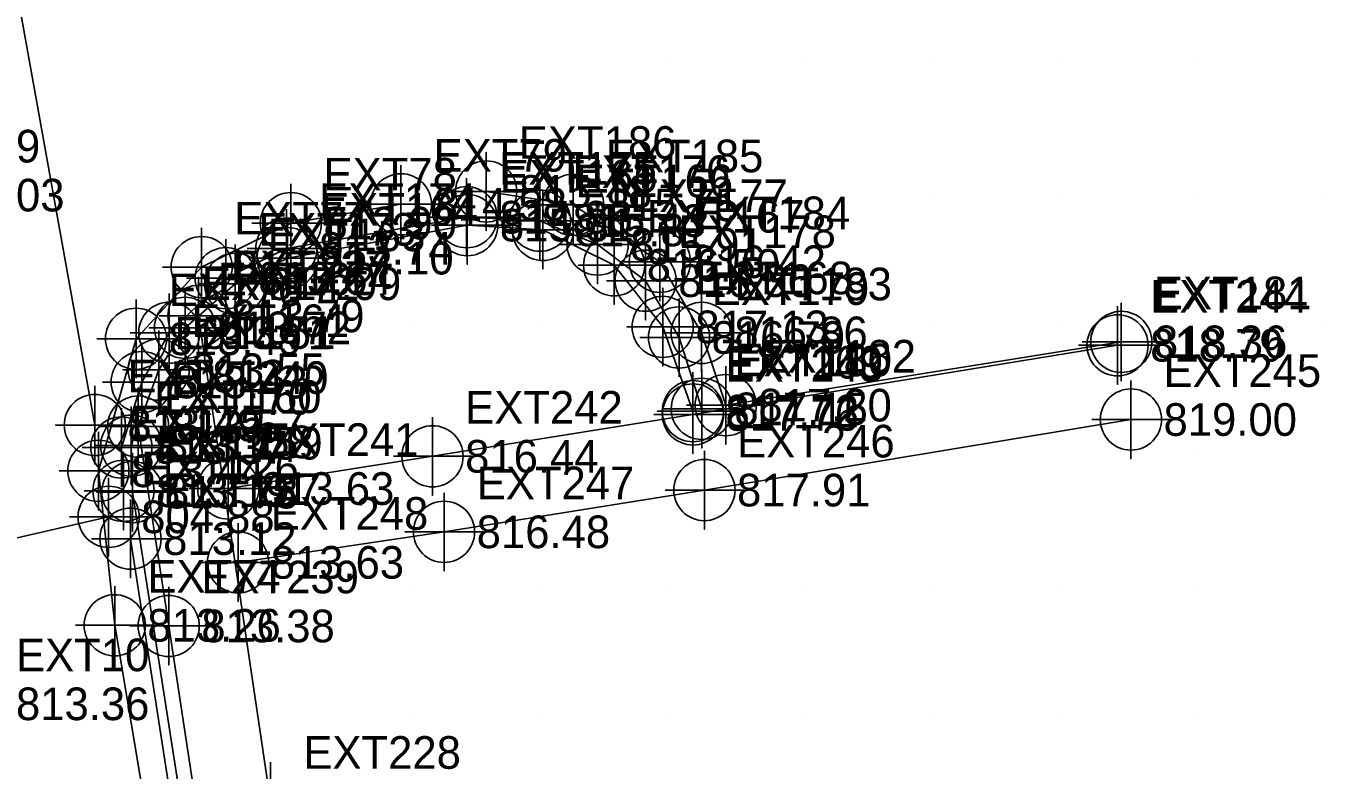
# Model space of a CAD drawing. Extents: x 1762120 to 1766775, y 709485 to 712965.
# Drawn here: x 1763810.5 to 1763910, y 712815.9 to 712872.9 of the extents above; entities that cross this region are included whole.
import ezdxf

# ---------------------------------------------------------------- set-up
doc = ezdxf.new("R2010")
doc.units = 0
for name, color, linetype in [('Exist DTM Drainline', 7, 'Continuous'), ('Exist DTM Drainline Cogo Elevation', 7, 'Continuous'), ('Exist DTM Drainline Cogo Number', 7, 'Continuous'), ('Exist DTM Drainline Cogo Point CELL', 7, 'Continuous'), ('Exist DTM QL2 LIDAR Elevation Point', 7, 'Continuous'), ('Exist Roads Curbs', 7, 'Continuous'), ('Exist Roads Curbs Cogo Elevation', 7, 'Continuous'), ('Exist Roads Curbs Cogo Number', 7, 'Continuous'), ('Exist Roads Curbs Cogo Point CELL', 7, 'Continuous'), ('Exist Roads EOP', 7, 'Continuous'), ('Exist Roads EOP Cogo Elevation', 7, 'Continuous'), ('Exist Roads EOP Cogo Number', 7, 'Continuous'), ('Exist Roads EOP Cogo Point CELL', 7, 'Continuous'), ('Exist Roads EOP Other', 7, 'Continuous'), ('Exist Roads EOP Other Cogo Elevation', 7, 'Continuous'), ('Exist Roads EOP Other Cogo Number', 7, 'Continuous'), ('Exist Roads EOP Other Cogo Point CELL', 7, 'Continuous'), ('Exist Roads EOT', 7, 'Continuous'), ('Exist Roads EOT Cogo Elevation', 7, 'Continuous'), ('Exist Roads EOT Cogo Number', 7, 'Continuous'), ('Exist Roads EOT Cogo Point CELL', 7, 'Continuous'), ('Exist Structure Minor Pipes RCP 15 Inch', 7, 'Continuous'), ('Exist Structure Minor Pipes RCP 15 Inch Cogo Elevation', 7, 'Continuous'), ('Exist Structure Minor Pipes RCP 15 Inch Cogo Number', 7, 'Continuous'), ('Exist Structure Minor Pipes RCP 15 Inch Cogo Point CELL', 7, 'Continuous')]:
    doc.layers.add(name, color=color, linetype=linetype)

msp = doc.modelspace()

# ---------------------------------------------------------------- linework, layer by layer
at = {"layer": 'Exist DTM Drainline'}
for points in [[(1763817.989, 712837.279), (1763817.834, 712840.601), (1763819.388, 712845.611), (1763821.503, 712849.398), (1763825.83, 712853.572), (1763830.477, 712855.852), (1763844.289, 712858.245), (1763849.91, 712857.978), (1763854.328, 712856.151), (1763858.009, 712853.381), (1763860.57, 712849.03), (1763862.311, 712843.559)], [(1763888.176, 712675.965), (1763883.465, 712673.426), (1763879.421, 712672.239), (1763861.295, 712669.219), (1763855.834, 712669.139), (1763849.992, 712671.404), (1763845.815, 712675.27), (1763843.641, 712680.197), (1763837.254, 712719.085), (1763830.877, 712756.626), (1763824.422, 712795.511), (1763818.53, 712833.611)]]:
    msp.add_lwpolyline(points, dxfattribs=at)
at = {"layer": 'Exist DTM Drainline Cogo Point CELL'}
for points in [[(1763844.289, 712861.245), (1763844.289, 712855.245), (1763844.289, 712858.245), (1763847.289, 712858.245), (1763841.289, 712858.245)], [(1763849.91, 712860.978), (1763849.91, 712854.978), (1763849.91, 712857.978), (1763852.91, 712857.978), (1763846.91, 712857.978)], [(1763830.477, 712858.852), (1763830.477, 712852.852), (1763830.477, 712855.852), (1763833.477, 712855.852), (1763827.477, 712855.852)], [(1763854.328, 712859.151), (1763854.328, 712853.151), (1763854.328, 712856.151), (1763857.328, 712856.151), (1763851.328, 712856.151)], [(1763825.83, 712856.572), (1763825.83, 712850.572), (1763825.83, 712853.572), (1763828.83, 712853.572), (1763822.83, 712853.572)], [(1763858.009, 712856.381), (1763858.009, 712850.381), (1763858.009, 712853.381), (1763861.009, 712853.381), (1763855.009, 712853.381)], [(1763821.503, 712852.398), (1763821.503, 712846.398), (1763821.503, 712849.398), (1763824.503, 712849.398), (1763818.503, 712849.398)], [(1763860.57, 712852.03), (1763860.57, 712846.03), (1763860.57, 712849.03), (1763863.57, 712849.03), (1763857.57, 712849.03)], [(1763819.388, 712848.611), (1763819.388, 712842.611), (1763819.388, 712845.611), (1763822.388, 712845.611), (1763816.388, 712845.611)], [(1763862.311, 712846.559), (1763862.311, 712840.559), (1763862.311, 712843.559), (1763865.311, 712843.559), (1763859.311, 712843.559)], [(1763817.834, 712843.601), (1763817.834, 712837.601), (1763817.834, 712840.601), (1763820.834, 712840.601), (1763814.834, 712840.601)], [(1763817.989, 712840.279), (1763817.989, 712834.279), (1763817.989, 712837.279), (1763820.989, 712837.279), (1763814.989, 712837.279)], [(1763818.53, 712836.611), (1763818.53, 712830.611), (1763818.53, 712833.611), (1763821.53, 712833.611), (1763815.53, 712833.611)]]:
    msp.add_lwpolyline(points, dxfattribs=at)
for centre in [(1763844.289, 712858.245), (1763849.91, 712857.978), (1763830.477, 712855.852), (1763854.328, 712856.151), (1763825.83, 712853.572), (1763858.009, 712853.381), (1763821.503, 712849.398), (1763860.57, 712849.03), (1763819.388, 712845.611), (1763862.311, 712843.559), (1763817.834, 712840.601), (1763817.989, 712837.279), (1763818.53, 712833.611)]:
    msp.add_circle(centre, 2.344, dxfattribs=at)
at = {"layer": 'Exist DTM QL2 LIDAR Elevation Point'}
for p, q in [((1763860, 712870), (1763860, 712870)), ((1763870, 712870), (1763870, 712870)), ((1763880, 712870), (1763880, 712870)), ((1763890, 712870), (1763890, 712870)), ((1763900, 712870), (1763900, 712870)), ((1763860, 712860), (1763860, 712860)), ((1763870, 712860), (1763870, 712860)), ((1763880, 712860), (1763880, 712860)), ((1763890, 712860), (1763890, 712860)), ((1763900, 712860), (1763900, 712860)), ((1763910, 712860), (1763910, 712860)), ((1763840, 712850), (1763840, 712850)), ((1763850, 712850), (1763850, 712850)), ((1763880, 712850), (1763880, 712850)), ((1763890, 712850), (1763890, 712850)), ((1763900, 712850), (1763900, 712850)), ((1763910, 712850), (1763910, 712850)), ((1763840, 712840), (1763840, 712840)), ((1763900, 712840), (1763900, 712840)), ((1763840, 712830), (1763840, 712830)), ((1763850, 712830), (1763850, 712830)), ((1763860, 712830), (1763860, 712830)), ((1763870, 712830), (1763870, 712830)), ((1763880, 712830), (1763880, 712830)), ((1763890, 712830), (1763890, 712830)), ((1763900, 712830), (1763900, 712830)), ((1763840, 712820), (1763840, 712820)), ((1763850, 712820), (1763850, 712820)), ((1763860, 712820), (1763860, 712820)), ((1763870, 712820), (1763870, 712820)), ((1763880, 712820), (1763880, 712820)), ((1763890, 712820), (1763890, 712820)), ((1763900, 712820), (1763900, 712820))]:
    msp.add_line(p, q, dxfattribs=at)
at = {"layer": 'Exist Roads Curbs'}
msp.add_lwpolyline([(1763887.913, 712676.609), (1763883.105, 712673.993), (1763879.529, 712672.953), (1763861.13, 712669.797), (1763855.716, 712669.958), (1763851.546, 712671.351), (1763848.135, 712673.751), (1763845.524, 712677.19), (1763844.339, 712680.601), (1763837.881, 712719.135), (1763831.693, 712756.599), (1763825.169, 712795.603), (1763818.676, 712837.176), (1763818.589, 712840.745), (1763820.694, 712846.562), (1763822.71, 712849.767), (1763826.551, 712853.145), (1763830.571, 712855.107), (1763844.339, 712857.64), (1763850.134, 712857.271), (1763855.594, 712854.564), (1763859.316, 712849.842), (1763861.632, 712843.383)], dxfattribs=at)
at = {"layer": 'Exist Roads Curbs Cogo Point CELL'}
for points in [[(1763844.339, 712860.64), (1763844.339, 712854.64), (1763844.339, 712857.64), (1763841.609, 712857.64), (1763847.339, 712857.64)], [(1763850.134, 712860.271), (1763850.134, 712854.271), (1763850.134, 712857.271), (1763847.404, 712857.271), (1763853.134, 712857.271)], [(1763830.571, 712858.107), (1763830.571, 712852.107), (1763830.571, 712855.107), (1763827.841, 712855.107), (1763833.571, 712855.107)], [(1763855.594, 712857.564), (1763855.594, 712851.564), (1763855.594, 712854.564), (1763852.864, 712854.564), (1763858.594, 712854.564)], [(1763826.551, 712856.145), (1763826.551, 712850.145), (1763826.551, 712853.145), (1763823.821, 712853.145), (1763829.551, 712853.145)], [(1763822.71, 712852.767), (1763822.71, 712846.767), (1763822.71, 712849.767), (1763819.98, 712849.767), (1763825.71, 712849.767)], [(1763859.316, 712852.842), (1763859.316, 712846.842), (1763859.316, 712849.842), (1763856.586, 712849.842), (1763862.316, 712849.842)], [(1763820.694, 712849.562), (1763820.694, 712843.562), (1763820.694, 712846.562), (1763817.964, 712846.562), (1763823.694, 712846.562)], [(1763861.632, 712846.383), (1763861.632, 712840.383), (1763861.632, 712843.383), (1763858.902, 712843.383), (1763864.632, 712843.383)], [(1763818.589, 712843.745), (1763818.589, 712837.745), (1763818.589, 712840.745), (1763815.859, 712840.745), (1763821.589, 712840.745)], [(1763818.676, 712840.176), (1763818.676, 712834.176), (1763818.676, 712837.176), (1763815.946, 712837.176), (1763821.676, 712837.176)]]:
    msp.add_lwpolyline(points, dxfattribs=at)
for centre in [(1763844.339, 712857.64), (1763850.134, 712857.271), (1763830.571, 712855.107), (1763855.594, 712854.564), (1763826.551, 712853.145), (1763822.71, 712849.767), (1763859.316, 712849.842), (1763820.694, 712846.562), (1763861.632, 712843.383), (1763818.589, 712840.745), (1763818.676, 712837.176)]:
    msp.add_circle(centre, 2.344, dxfattribs=at)
at = {"layer": 'Exist Roads EOP'}
for points in [[(1763894.461, 712848.693), (1763864.149, 712843.843), (1763862.303, 712849.38), (1763859.101, 712854.83), (1763852.452, 712859.194), (1763845.79, 712860.221)], [(1763872.939, 712669.264), (1763861.771, 712667.397), (1763856.129, 712667.205), (1763850.394, 712669.068), (1763848.283, 712670.385), (1763843.436, 712675.406), (1763841.767, 712679.86), (1763835.931, 712715.544), (1763829.184, 712756.072), (1763822.427, 712796.443), (1763817.324, 712826.974), (1763816.07, 712838.811), (1763818.954, 712848.93), (1763823.982, 712854.424), (1763830.822, 712857.794), (1763839.256, 712859.239)]]:
    msp.add_lwpolyline(points, dxfattribs=at)
at = {"layer": 'Exist Roads EOP Cogo Point CELL'}
for points in [[(1763845.79, 712863.221), (1763845.79, 712857.221), (1763845.79, 712860.221), (1763848.79, 712860.221), (1763842.79, 712860.221)], [(1763839.256, 712862.239), (1763839.256, 712856.239), (1763839.256, 712859.239), (1763842.256, 712859.239), (1763836.256, 712859.239)], [(1763852.452, 712862.194), (1763852.452, 712856.194), (1763852.452, 712859.194), (1763855.452, 712859.194), (1763849.452, 712859.194)], [(1763830.822, 712860.794), (1763830.822, 712854.794), (1763830.822, 712857.794), (1763833.822, 712857.794), (1763827.822, 712857.794)], [(1763859.101, 712857.83), (1763859.101, 712851.83), (1763859.101, 712854.83), (1763862.101, 712854.83), (1763856.101, 712854.83)], [(1763823.982, 712857.424), (1763823.982, 712851.424), (1763823.982, 712854.424), (1763826.982, 712854.424), (1763820.982, 712854.424)], [(1763818.954, 712851.93), (1763818.954, 712845.93), (1763818.954, 712848.93), (1763821.954, 712848.93), (1763815.954, 712848.93)], [(1763862.303, 712852.38), (1763862.303, 712846.38), (1763862.303, 712849.38), (1763865.303, 712849.38), (1763859.303, 712849.38)], [(1763894.461, 712851.693), (1763894.461, 712845.693), (1763894.461, 712848.693), (1763897.461, 712848.693), (1763891.461, 712848.693)], [(1763864.149, 712846.843), (1763864.149, 712840.843), (1763864.149, 712843.843), (1763867.149, 712843.843), (1763861.149, 712843.843)], [(1763816.07, 712841.811), (1763816.07, 712835.811), (1763816.07, 712838.811), (1763819.07, 712838.811), (1763813.07, 712838.811)], [(1763817.324, 712829.974), (1763817.324, 712823.974), (1763817.324, 712826.974), (1763820.324, 712826.974), (1763814.324, 712826.974)]]:
    msp.add_lwpolyline(points, dxfattribs=at)
for centre in [(1763845.79, 712860.221), (1763839.256, 712859.239), (1763852.452, 712859.194), (1763830.822, 712857.794), (1763859.101, 712854.83), (1763823.982, 712854.424), (1763818.954, 712848.93), (1763862.303, 712849.38), (1763894.461, 712848.693), (1763864.149, 712843.843), (1763816.07, 712838.811), (1763817.324, 712826.974)]:
    msp.add_circle(centre, 2.344, dxfattribs=at)
at = {"layer": 'Exist Roads EOP Other'}
for points in [[(1763823.74, 712850.658), (1763829.272, 712813.477), (1763835.791, 712775.327), (1763842.869, 712737.848), (1763850.058, 712700.088), (1763853.731, 712680.407), (1763855.596, 712670.266)], [(1763826.023, 712837.454), (1763841.676, 712839.928), (1763861.632, 712843.133), (1763894.176, 712848.43)], [(1763848.821, 712673.422), (1763847.825, 712679.985), (1763840.398, 712719.751), (1763833.777, 712754.373), (1763826.475, 712793.95), (1763821.461, 712826.921), (1763819.116, 712842.201)], [(1763895.199, 712842.743), (1763862.514, 712837.335), (1763842.562, 712834.135), (1763826.771, 712831.794)]]:
    msp.add_lwpolyline(points, dxfattribs=at)
at = {"layer": 'Exist Roads EOP Other Cogo Point CELL'}
for points in [[(1763823.737, 712853.681), (1763823.737, 712847.681), (1763823.737, 712850.681), (1763826.737, 712850.681), (1763820.737, 712850.681)], [(1763894.176, 712851.43), (1763894.176, 712845.43), (1763894.176, 712848.43), (1763897.176, 712848.43), (1763891.176, 712848.43)], [(1763861.632, 712846.133), (1763861.632, 712840.133), (1763861.632, 712843.133), (1763864.632, 712843.133), (1763858.632, 712843.133)], [(1763819.116, 712845.202), (1763819.116, 712839.202), (1763819.116, 712842.202), (1763822.116, 712842.202), (1763816.116, 712842.202)], [(1763895.199, 712845.743), (1763895.199, 712839.743), (1763895.199, 712842.743), (1763898.199, 712842.743), (1763892.199, 712842.743)], [(1763841.676, 712842.928), (1763841.676, 712836.928), (1763841.676, 712839.928), (1763844.676, 712839.928), (1763838.676, 712839.928)], [(1763826.023, 712840.454), (1763826.023, 712834.454), (1763826.023, 712837.454), (1763829.023, 712837.454), (1763823.023, 712837.454)], [(1763862.514, 712840.335), (1763862.514, 712834.335), (1763862.514, 712837.335), (1763865.514, 712837.335), (1763859.514, 712837.335)], [(1763842.562, 712837.135), (1763842.562, 712831.135), (1763842.562, 712834.135), (1763845.562, 712834.135), (1763839.562, 712834.135)], [(1763826.771, 712834.794), (1763826.771, 712828.794), (1763826.771, 712831.794), (1763829.771, 712831.794), (1763823.771, 712831.794)], [(1763821.461, 712829.921), (1763821.461, 712823.921), (1763821.461, 712826.921), (1763824.461, 712826.921), (1763818.461, 712826.921)], [(1763829.272, 712816.477), (1763829.272, 712810.477), (1763829.272, 712813.477), (1763832.272, 712813.477), (1763826.272, 712813.477)]]:
    msp.add_lwpolyline(points, dxfattribs=at)
for centre in [(1763823.737, 712850.681), (1763894.176, 712848.43), (1763861.632, 712843.133), (1763895.199, 712842.743), (1763819.116, 712842.202), (1763841.676, 712839.928), (1763826.023, 712837.454), (1763862.514, 712837.335), (1763842.562, 712834.135), (1763826.771, 712831.794), (1763821.461, 712826.921)]:
    msp.add_circle(centre, 2.344, dxfattribs=at)
at = {"layer": 'Exist Roads EOT'}
msp.add_line((1763815.792, 712842.322), (1763808.078, 712885.317), dxfattribs=at)
at = {"layer": 'Exist Roads EOT Cogo Point CELL'}
msp.add_lwpolyline([(1763815.792, 712845.322), (1763815.792, 712839.322), (1763815.792, 712842.322), (1763812.792, 712842.322), (1763818.792, 712842.322)], dxfattribs=at)
msp.add_circle((1763815.792, 712842.322), 2.344, dxfattribs=at)
at = {"layer": 'Exist Structure Minor Pipes RCP 15 Inch'}
msp.add_line((1763816.852, 712835.285), (1763782.661, 712827.424), dxfattribs=at)
at = {"layer": 'Exist Structure Minor Pipes RCP 15 Inch Cogo Point CELL'}
msp.add_lwpolyline([(1763816.852, 712838.285), (1763816.852, 712832.285), (1763816.852, 712835.285), (1763819.852, 712835.285), (1763813.852, 712835.285)], dxfattribs=at)
msp.add_circle((1763816.852, 712835.285), 2.344, dxfattribs=at)

# ---------------------------------------------------------------- texts
at = {"layer": 'Exist DTM Drainline Cogo Elevation'}
for s, p in [('814.88', (1763846.789, 712856.995)), ('815.43', (1763852.41, 712856.728)), ('813.74', (1763832.977, 712854.602)), ('815.91', (1763856.828, 712854.901)), ('813.64', (1763828.33, 712852.322)), ('816.36', (1763860.509, 712852.131)), ('813.51', (1763824.003, 712848.148)), ('816.79', (1763863.07, 712847.78)), ('813.43', (1763821.888, 712844.361)), ('817.15', (1763864.811, 712842.309)), ('813.37', (1763820.334, 712839.351)), ('813.19', (1763820.489, 712836.029)), ('813.12', (1763821.03, 712832.361))]:
    msp.add_text(s, height=2.5, dxfattribs=at).set_placement(p)
at = {"layer": 'Exist DTM Drainline Cogo Number'}
for s, p in [('EXT175', (1763846.789, 712860.745)), ('EXT176', (1763852.41, 712860.478)), ('EXT174', (1763832.977, 712858.352)), ('EXT177', (1763856.828, 712858.651)), ('EXT173', (1763828.33, 712856.072)), ('EXT178', (1763860.509, 712855.881)), ('EXT172', (1763824.003, 712851.898)), ('EXT179', (1763863.07, 712851.53)), ('EXT171', (1763821.888, 712848.111)), ('EXT180', (1763864.811, 712846.059)), ('EXT170', (1763820.334, 712843.101)), ('EXT158', (1763820.489, 712839.779)), ('EXT157', (1763821.03, 712836.111))]:
    msp.add_text(s, height=2.5, dxfattribs=at).set_placement(p)
at = {"layer": 'Exist Roads Curbs Cogo Elevation'}
for s, p in [('815.31', (1763846.839, 712856.39)), ('815.87', (1763852.634, 712856.021)), ('814.10', (1763833.071, 712853.857)), ('816.50', (1763858.094, 712853.314)), ('814.09', (1763829.051, 712851.895)), ('813.72', (1763825.21, 712848.517)), ('817.13', (1763861.816, 712848.592)), ('813.55', (1763823.194, 712845.312)), ('817.72', (1763864.132, 712842.133)), ('813.74', (1763821.089, 712839.495)), ('813.78', (1763821.176, 712835.926))]:
    msp.add_text(s, height=2.5, dxfattribs=at).set_placement(p)
at = {"layer": 'Exist Roads Curbs Cogo Number'}
for s, p in [('EXT165', (1763846.839, 712860.14)), ('EXT166', (1763852.634, 712859.771)), ('EXT164', (1763833.071, 712857.607)), ('EXT167', (1763858.094, 712857.064)), ('EXT163', (1763829.051, 712855.645)), ('EXT168', (1763861.816, 712852.342)), ('EXT162', (1763825.21, 712852.267)), ('EXT161', (1763823.194, 712849.062)), ('EXT169', (1763864.132, 712845.883)), ('EXT160', (1763821.089, 712843.245)), ('EXT159', (1763821.176, 712839.676))]:
    msp.add_text(s, height=2.5, dxfattribs=at).set_placement(p)
at = {"layer": 'Exist Roads EOP Cogo Elevation'}
for s, p in [('815.18', (1763848.29, 712858.971)), ('814.58', (1763841.756, 712857.989)), ('815.75', (1763854.952, 712857.944)), ('813.90', (1763833.322, 712856.544)), ('816.42', (1763861.601, 712853.58)), ('813.72', (1763826.482, 712853.174)), ('813.49', (1763821.454, 712847.68)), ('816.86', (1763864.803, 712848.13)), ('818.36', (1763896.961, 712847.443)), ('817.20', (1763866.649, 712842.593)), ('813.44', (1763818.57, 712837.561)), ('813.26', (1763819.824, 712825.724))]:
    msp.add_text(s, height=2.5, dxfattribs=at).set_placement(p)
at = {"layer": 'Exist Roads EOP Cogo Number'}
for s, p in [('EXT186', (1763848.29, 712862.721)), ('EXT79', (1763841.756, 712861.739)), ('EXT185', (1763854.952, 712861.694)), ('EXT78', (1763833.322, 712860.294)), ('EXT184', (1763861.601, 712857.33)), ('EXT77', (1763826.482, 712856.924)), ('EXT76', (1763821.454, 712851.43)), ('EXT183', (1763864.803, 712851.88)), ('EXT181', (1763896.961, 712851.193)), ('EXT182', (1763866.649, 712846.343)), ('EXT75', (1763818.57, 712841.311)), ('EXT74', (1763819.824, 712829.474))]:
    msp.add_text(s, height=2.5, dxfattribs=at).set_placement(p)
at = {"layer": 'Exist Roads EOP Other Cogo Elevation'}
for s, p in [('813.79', (1763826.237, 712849.431)), ('818.79', (1763896.676, 712847.18)), ('817.76', (1763864.132, 712841.883)), ('819.00', (1763897.699, 712841.493)), ('813.57', (1763821.616, 712840.952)), ('816.44', (1763844.176, 712838.678)), ('813.63', (1763828.523, 712836.204)), ('817.91', (1763865.014, 712836.085)), ('816.48', (1763845.062, 712832.885)), ('813.63', (1763829.271, 712830.544)), ('813.38', (1763823.961, 712825.671))]:
    msp.add_text(s, height=2.5, dxfattribs=at).set_placement(p)
at = {"layer": 'Exist Roads EOP Other Cogo Number'}
for s, p in [('EXT227', (1763826.237, 712853.181)), ('EXT244', (1763896.676, 712850.93)), ('EXT243', (1763864.132, 712845.633)), ('EXT240', (1763821.616, 712844.702)), ('EXT245', (1763897.699, 712845.243)), ('EXT242', (1763844.176, 712842.428)), ('EXT241', (1763828.523, 712839.954)), ('EXT246', (1763865.014, 712839.835)), ('EXT247', (1763845.062, 712836.635)), ('EXT248', (1763829.271, 712834.294)), ('EXT239', (1763823.961, 712829.421)), ('EXT228', (1763831.772, 712815.977))]:
    msp.add_text(s, height=2.5, dxfattribs=at).set_placement(p)
at = {"layer": 'Exist Roads EOT Cogo Elevation'}
for s, p in [('814.03', (1763803.25, 712858.692)), ('813.49', (1763818.292, 712841.072)), ('813.36', (1763809.754, 712819.705))]:
    msp.add_text(s, height=2.5, dxfattribs=at).set_placement(p)
at = {"layer": 'Exist Roads EOT Cogo Number'}
for s, p in [('EXT9', (1763803.25, 712862.442)), ('EXT813', (1763818.292, 712844.822)), ('EXT10', (1763809.754, 712823.455))]:
    msp.add_text(s, height=2.5, dxfattribs=at).set_placement(p)
at = {"layer": 'Exist Structure Minor Pipes RCP 15 Inch Cogo Elevation'}
msp.add_text('804.88', height=2.5, dxfattribs=at).set_placement((1763819.352, 712834.035))
at = {"layer": 'Exist Structure Minor Pipes RCP 15 Inch Cogo Number'}
msp.add_text('EXT126', height=2.5, dxfattribs=at).set_placement((1763819.352, 712837.785))

doc.saveas('drawing.dxf')
